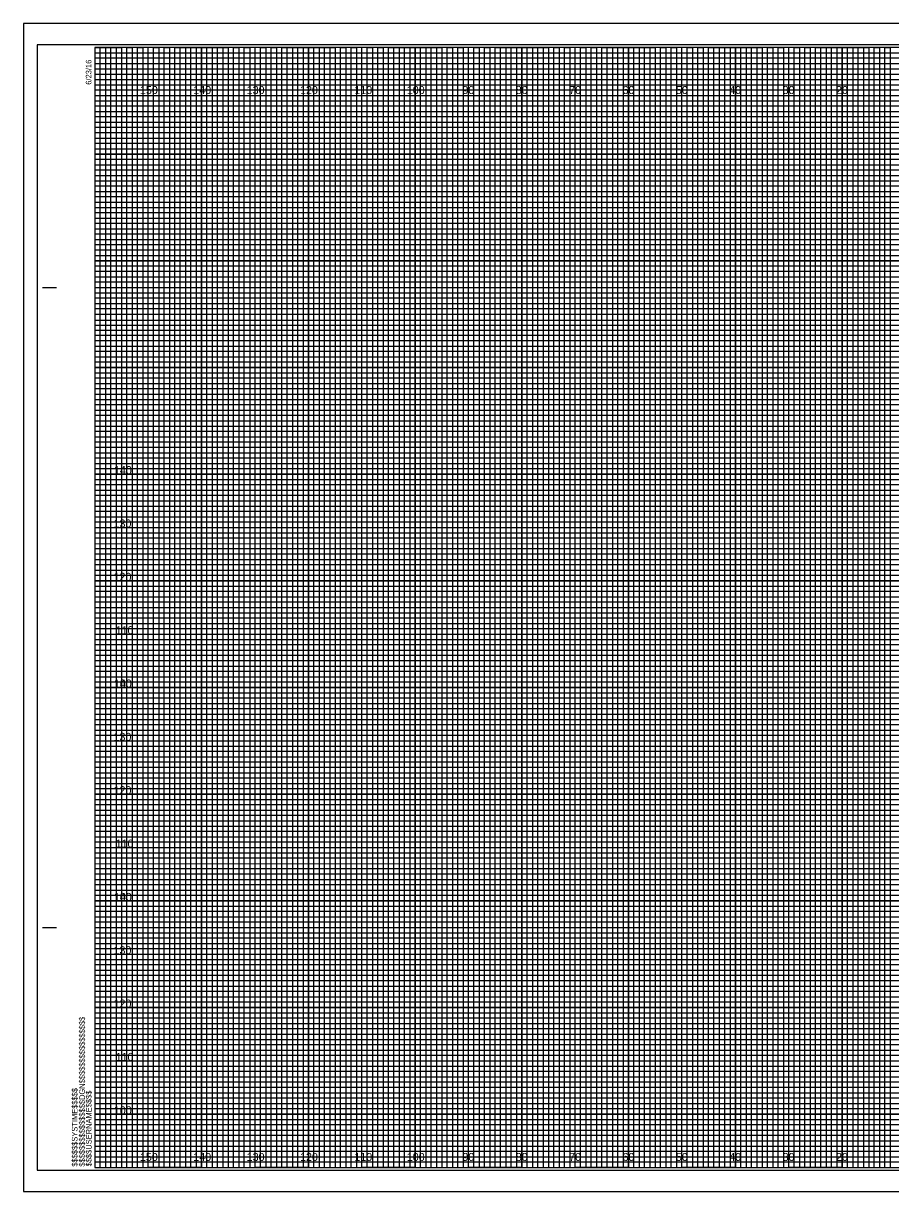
# Model space of a CAD drawing. Extents: x -13 to 323, y -5 to 215.
# Drawn here: x -13.4 to 149.1, y -4.5 to 214.5 of the extents above; entities that cross this region are included whole.
import ezdxf

# ---------------------------------------------------------------- set-up
doc = ezdxf.new("R2010")
doc.units = 0
for name, color, linetype in [('Prop XS Elevation Labels', 7, 'Continuous'), ('Prop XS Offset Labels', 7, 'Continuous'), ('Sheet Cross Section CELL', 7, 'Continuous'), ('Sheet Cross Section Grid Major CELL', 7, 'Continuous'), ('Sheet Cross Section Grid Middle CELL', 7, 'Continuous'), ('Sheet Cross Section Grid Minor 1 CELL', 7, 'Continuous'), ('Sheet Cross Section Grid Minor 2 CELL', 7, 'Continuous'), ('Sheet Cutting Line CELL', 7, 'Continuous'), ('Sheet DOT Grid CELL', 7, 'Continuous'), ('Sheet Plot Border Inside CELL', 7, 'Continuous'), ('Sheet Plot Border Outside CELL', 7, 'Continuous')]:
    doc.layers.add(name, color=color, linetype=linetype)

msp = doc.modelspace()

# ---------------------------------------------------------------- linework, layer by layer
at = {"layer": 'Sheet Cross Section CELL'}
for p, q in [((-9.8, 165), (-7.3, 165)), ((-9.7, 165), (-7.2, 165)), ((-9.8, 45), (-7.3, 45)), ((-9.7, 45), (-7.2, 45)), ((0, 0), (0, 0)), ((0, 0), (0, 0)), ((0, 0), (0, 0)), ((0, 0), (0, 0)), ((0, 0), (0, 0)), ((0, 0), (0, 0)), ((0, 0), (0, 0))]:
    msp.add_line(p, q, dxfattribs=at)
msp.add_lwpolyline([(320, 210), (0, 210), (0, 0), (320, 0)], close=True, dxfattribs=at)
at = {"layer": 'Sheet Cross Section Grid Major CELL'}
for p, q in [((10, 210), (0, 210)), ((10, 0), (10, 210)), ((30, 210), (20, 210)), ((20, 210), (20, 0)), ((30, 0), (30, 210)), ((50, 210), (40, 210)), ((40, 210), (40, 0)), ((50, 0), (50, 210)), ((70, 210), (60, 210)), ((60, 210), (60, 0)), ((70, 0), (70, 210)), ((90, 210), (80, 210)), ((80, 210), (80, 0)), ((90, 0), (90, 210)), ((110, 210), (100, 210)), ((100, 210), (100, 0)), ((110, 0), (110, 210)), ((130, 210), (120, 210)), ((120, 210), (120, 0)), ((130, 0), (130, 210)), ((150, 210), (140, 210)), ((140, 210), (140, 0)), ((20, 0), (10, 0)), ((40, 0), (30, 0)), ((60, 0), (50, 0)), ((80, 0), (70, 0)), ((100, 0), (90, 0)), ((120, 0), (110, 0)), ((140, 0), (130, 0))]:
    msp.add_line(p, q, dxfattribs=at)
for points in [[(0, 200), (320, 200), (320, 190), (0, 190)], [(0, 180), (320, 180), (320, 170), (0, 170)], [(0, 160), (320, 160), (320, 150), (0, 150)], [(0, 140), (320, 140), (320, 130), (0, 130)], [(0, 120), (320, 120), (320, 110), (0, 110)], [(0, 100), (320, 100), (320, 90), (0, 90)], [(0, 80), (320, 80), (320, 70), (0, 70)], [(0, 60), (320, 60), (320, 50), (0, 50)], [(0, 40), (320, 40), (320, 30), (0, 30)], [(0, 20), (320, 20), (320, 10), (0, 10)]]:
    msp.add_lwpolyline(points, dxfattribs=at)
at = {"layer": 'Sheet Cross Section Grid Middle CELL'}
for points in [[(0, 210), (5, 210), (5, 0), (15, 0), (15, 210), (25, 210), (25, 0), (35, 0), (35, 210), (45, 210), (45, 0), (55, 0), (55, 210), (65, 210), (65, 0), (75, 0), (75, 210), (85, 210), (85, 0), (95, 0), (95, 210), (105, 210), (105, 0), (115, 0), (115, 210), (125, 210), (125, 0), (135, 0), (135, 210), (145, 210), (145, 0), (155, 0)], [(0, 205), (275, 205)], [(0, 185), (320, 185), (320, 195), (0, 195)], [(0, 165), (320, 165), (320, 175), (0, 175)], [(0, 145), (320, 145), (320, 155), (0, 155)], [(0, 125), (320, 125), (320, 135), (0, 135)], [(0, 105), (320, 105), (320, 115), (0, 115)], [(0, 85), (320, 85), (320, 95), (0, 95)], [(0, 65), (320, 65), (320, 75), (0, 75)], [(0, 45), (320, 45), (320, 55), (0, 55)], [(0, 25), (320, 25), (320, 35), (0, 35)], [(0, 5), (320, 5), (320, 15), (0, 15)]]:
    msp.add_lwpolyline(points, dxfattribs=at)
at = {"layer": 'Sheet Cross Section Grid Minor 1 CELL'}
for p, q in [((0, 209), (260, 209)), ((260, 207.98), (0, 207.98)), ((0, 207.98), (0, 207)), ((0, 207), (260, 207)), ((260, 205.89), (0, 205.89)), ((0, 205.89), (0, 204)), ((0, 204), (320, 204))]:
    msp.add_line(p, q, dxfattribs=at)
for points in [[(0, 203), (270, 203), (320, 203), (320, 202), (0, 202)], [(0, 201), (320, 201), (320, 199), (0, 199)], [(0, 198), (320, 198), (320, 197), (0, 196.98)], [(0, 196), (320, 196), (320, 194), (0, 194)], [(0, 193), (320, 193), (320, 192), (0, 192)], [(0, 191), (320, 191), (320, 189), (0, 189)], [(0, 188), (320, 188), (320, 187), (0, 187)], [(0, 186), (320, 186), (320, 184), (0, 184)], [(0, 183), (320, 183), (320, 182), (0, 182)], [(0, 181), (320, 181), (320, 179), (0, 179)], [(0, 178), (320, 178), (320, 177), (0, 177)], [(0, 176), (320, 176), (320, 173.95), (320, 173), (320, 172), (0, 172)], [(0, 174), (320, 174), (320, 173), (0, 173)], [(0, 171), (320, 171), (320, 169), (0, 169.03)], [(0, 169.03), (320, 169), (320, 168), (0, 168)], [(0, 167), (320, 167), (320, 166), (0, 166)], [(0, 164), (320, 164), (320, 163), (0, 163)], [(0, 162), (320, 162), (320, 161), (0, 161)], [(-0.07, 158.89), (320, 158.89), (320, 157.88), (-0.07, 157.88)], [(0, 157), (320, 157), (320, 156), (0, 156)], [(0, 154), (320, 154), (320, 153), (0, 153)], [(0, 152), (320, 152), (320, 151), (0, 151)], [(0, 149), (320, 149), (320, 148), (0, 148)], [(0, 147), (320, 147), (320, 146), (0, 146)], [(0, 144), (320, 144), (320, 143), (0, 143)], [(0, 142), (320, 142), (320, 141), (0, 141)], [(0, 139), (320, 139), (319.99, 137.98), (0, 138)], [(0, 137), (320, 137), (320, 136), (0, 136)], [(0, 134), (320, 134), (320, 133), (0, 133)], [(0, 132), (320, 132), (320, 131), (0, 131)], [(0, 129), (320, 129), (320, 128), (0, 128)], [(0, 127), (320, 127), (320, 126), (0, 126)], [(0, 124), (320, 124), (320, 123), (0, 123)], [(0, 122), (320, 122), (320, 121), (0, 121)], [(0, 119), (320, 119), (320, 118), (0, 118)], [(0, 116.99), (320.07, 116.91), (320, 116), (0, 116)], [(0, 114), (320, 114), (320, 113), (0, 113)], [(0, 112), (320, 112), (320, 111), (0, 111)], [(0, 109), (320, 109), (320, 108), (0, 108)], [(0, 107), (320, 107), (320, 106), (0, 106)], [(0, 104), (320, 104), (320, 103), (0, 103)], [(0, 102), (320, 102), (320, 101), (0, 101)], [(0, 99), (320, 99), (320, 98), (0, 98)], [(0, 97), (320, 97), (320, 96), (0, 96)], [(0, 94), (320, 94), (320, 93), (0, 93)], [(0, 92), (320, 92), (320, 91), (0, 91)], [(0, 89), (320, 89), (320, 88), (0, 88)], [(0, 87), (320, 87), (320, 86), (0, 86)], [(0, 84), (320, 84), (320, 83), (0, 83)], [(0, 82), (320, 82), (320, 81), (0, 81)], [(0, 79), (320, 79), (319.99, 77.98), (0, 78)], [(0, 77), (320, 77), (320, 76), (0, 76)], [(0, 74), (320, 74), (320, 73), (0, 73)], [(0, 72), (320, 72), (320, 71), (0, 71)], [(0, 69), (320, 69), (320, 68), (0, 68)], [(0, 67), (320, 67), (320, 66), (0, 66)], [(0, 64), (320, 64), (320, 63), (0, 63)], [(0, 62), (320, 62), (320, 61), (0, 61)], [(0, 59), (320, 59), (320, 58), (0, 58)], [(0, 56.99), (320.07, 56.91), (320, 56), (0, 56)], [(0, 54), (320, 54), (320, 53), (0, 53)], [(0, 52), (320, 52), (320, 51), (0, 51)], [(0, 49), (320, 49), (320, 48), (0, 48)], [(0, 47), (320, 47), (320, 46), (0, 46)], [(0, 44), (320, 44), (320, 43), (0, 43)], [(0, 42), (320, 42), (320, 41), (0, 41)], [(0, 39), (320, 39), (320, 38), (0, 38)], [(0, 37), (320, 37), (320, 36), (0, 36)], [(0, 34), (320, 34), (320, 33), (0, 33)], [(0, 32), (320, 32), (320, 31), (0, 31)], [(0, 29), (320, 29), (320, 28), (0, 28)], [(0, 27), (320, 27), (320, 26), (0, 26)], [(0, 24), (320, 24), (320, 23), (0, 23)], [(0, 22), (320, 22), (320, 21), (0, 21)], [(0, 19), (320, 19), (320, 18), (0, 18)], [(0, 17), (320, 17), (320, 16), (0, 16)], [(0, 14), (320, 14), (320, 13), (0, 13)], [(0, 12), (320, 12), (320, 11), (0, 11)], [(0, 9), (320, 9), (320, 8), (0, 8)], [(0, 7), (320, 7), (320, 6), (0, 6)], [(0, 4), (320, 4), (320, 3), (0, 3)], [(0, 2), (320, 2), (320, 1), (0, 1)]]:
    msp.add_lwpolyline(points, dxfattribs=at)
at = {"layer": 'Sheet Cross Section Grid Minor 2 CELL'}
for points in [[(0, 0), (1, 0), (1, 210), (2, 210), (2, 0)], [(2, 0), (3, 0), (3, 210), (4, 210), (4, 0)], [(5, 0), (6, 0), (6, 210), (7, 210), (7, 0)], [(7, 0), (8, 0), (8, 210), (9, 210), (9, 0)], [(10, 0), (11, 0), (11, 210), (12, 210), (12, 0)], [(12, 0), (13, 0), (13, 210), (14, 210), (14, 0)], [(15, 0), (16, 0), (16, 210), (17, 210), (17, 0)], [(17, 0), (18, 0), (18, 210), (19, 210), (19, 0)], [(20, 0), (21, 0), (21, 210), (22, 210), (22, 0)], [(22, 0), (23, 0), (23, 210), (24, 210), (24, 0)], [(25, 0), (26, 0), (26, 210), (27, 210), (27, 0)], [(27, 0), (28, 0), (28, 210), (29, 210), (29, 0)], [(30, 0), (31, 0), (31, 210), (32, 210), (32, 0)], [(32, 0), (33, 0), (33, 210), (34, 210), (34, 0)], [(35, 0), (36, 0), (36, 210), (37, 210), (37, 0)], [(37, 0), (38, 0), (38, 210), (39, 210), (39, 0)], [(40, 0), (41, 0), (41, 210), (42, 210), (42, 0)], [(42, 0), (43, 0), (43, 210), (44, 210), (44, 0)], [(45, 0), (46, 0), (46, 210), (47, 210), (47, 0)], [(47, 0), (48, 0), (48, 210), (49, 210), (49, 0)], [(50, 0), (51, 0), (51, 210), (52, 210), (52, 0)], [(52, 0), (53, 0), (53, 210), (54, 210), (54, 0)], [(55, 0), (56, 0), (56, 210), (57, 210), (57, 0)], [(57, 0), (58, 0), (58, 210), (59, 210), (59, 0)], [(60, 0), (61, 0), (61, 210), (62, 210), (62, 0)], [(62, 0), (63, 0), (63, 210), (64, 210), (64, 0)], [(65, 0), (66, 0), (66, 210), (67, 210), (67, 0)], [(67, 0), (68, 0), (68, 210), (69, 210), (69, 0)], [(70, 0), (71, 0), (71, 210), (72, 210), (72, 0)], [(72, 0), (73, 0), (73, 210), (74, 210), (74, 0)], [(75, 0), (76, 0), (76, 210), (77, 210), (77, 0)], [(77, 0), (78, 0), (78, 210), (79, 210), (79, 0)], [(80, 0), (81, 0), (81, 210), (82, 210), (82, 0)], [(82, 0), (83, 0), (83, 210), (84, 210), (84, 0)], [(85, 0), (86, 0), (86, 210), (87, 210), (87, 0)], [(87, 0), (88, 0), (88, 210), (89, 210), (89, 0)], [(90, 0), (91, 0), (91, 210), (92, 210), (92, 0)], [(92, 0), (93, 0), (93, 210), (94, 210), (94, 0)], [(95, 0), (96, 0), (96, 210), (97, 210), (97, 0)], [(97, 0), (98, 0), (98, 210), (99, 210), (99, 0)], [(100, 0), (101, 0), (101, 210), (102, 210), (102, 0)], [(102, 0), (103, 0), (103, 210), (104, 210), (104, 0)], [(105, 0), (106, 0), (106, 210), (107, 210), (107, 0)], [(107, 0), (108, 0), (108, 210), (109, 210), (109, 0)], [(110, 0), (111, 0), (111, 210), (112, 210), (112, 0)], [(112, 0), (113, 0), (113, 210), (114, 210), (114, 0)], [(115, 0), (116, 0), (116, 210), (117, 210), (117, 0)], [(117, 0), (118, 0), (118, 210), (119, 210), (119, 0)], [(120, 0), (121, 0), (121, 210), (122, 210), (122, 0)], [(122, 0), (123, 0), (123, 210), (124, 210), (124, 0)], [(125, 0), (126, 0), (126, 210), (127, 210), (127, 0)], [(127, 0), (128, 0), (128, 210), (129, 210), (129, 0)], [(130, 0), (131, 0), (131, 210), (132, 210), (132, 0)], [(132, 0), (133, 0), (133, 210), (134, 210), (134, 0)], [(135, 0), (136, 0), (136, 210), (137, 210), (137, 0)], [(137, 0), (138, 0), (138, 210), (139, 210), (139, 0)], [(140, 0), (141, 0), (141, 210), (142, 210), (142, 0)], [(142, 0), (143, 0), (143, 210), (144, 210), (144, 0)], [(145, 0), (146, 0), (146, 210), (147, 210), (147, 0)], [(147, 0), (148, 0), (148, 210), (149, 210), (149, 0)]]:
    msp.add_lwpolyline(points, dxfattribs=at)
at = {"layer": 'Sheet Cutting Line CELL'}
for p, q in [((323.3, 214.5), (-13.4, 214.5)), ((-13.4, 214.5), (-13.4, -4.5)), ((-13.4, -4.5), (323.3, -4.5))]:
    msp.add_line(p, q, dxfattribs=at)
at = {"layer": 'Sheet DOT Grid CELL'}
for p, q in [((10, 0), (10, 210)), ((20, 0), (20, 210)), ((30, 0), (30, 210)), ((40, 0), (40, 210)), ((50, 0), (50, 210)), ((60, 0), (60, 210)), ((70, 0), (70, 210)), ((80, 0), (80, 210)), ((90, 0), (90, 210)), ((100, 0), (100, 210)), ((110, 0), (110, 210)), ((120, 0), (120, 210)), ((130, 0), (130, 210)), ((140, 0), (140, 210)), ((0, 200), (320, 200)), ((0, 190), (320, 190)), ((0, 180), (320, 180)), ((0, 170), (320, 170)), ((0, 160), (320, 160)), ((0, 150), (320, 150)), ((0, 140), (320, 140)), ((0, 130), (320, 130)), ((0, 120), (320, 120)), ((0, 110), (320, 110)), ((0, 100), (320, 100)), ((0, 90), (320, 90)), ((0, 80), (320, 80)), ((0, 70), (320, 70)), ((0, 60), (320, 60)), ((0, 50), (320, 50)), ((0, 40), (320, 40)), ((0, 30), (320, 30)), ((0, 20), (320, 20)), ((0, 10), (320, 10))]:
    msp.add_line(p, q, dxfattribs=at)
at = {"layer": 'Sheet Plot Border Inside CELL'}
msp.add_lwpolyline([(-10.8, -0.5), (322.4, -0.5), (322.4, 210.5), (-10.8, 210.5)], close=True, dxfattribs=at)
at = {"layer": 'Sheet Plot Border Outside CELL'}
msp.add_lwpolyline([(-13.4, -4.5), (323.3, -4.5), (323.3, 214.5), (-13.4, 214.5)], close=True, dxfattribs=at)

# ---------------------------------------------------------------- texts
at = {"layer": 'Prop XS Elevation Labels'}
for s, p in [('140', (3.57, 130)), ('130', (3.49, 120)), ('120', (3.5, 110)), ('110', (3.88, 100)), ('100', (3.55, 90)), ('140', (3.57, 90)), ('130', (3.49, 80)), ('120', (3.5, 70)), ('110', (3.88, 60)), ('100', (3.55, 50)), ('140', (3.57, 50)), ('130', (3.49, 40)), ('120', (3.5, 30)), ('110', (3.88, 20)), ('100', (3.55, 10))]:
    msp.add_text(s, height=1.5, dxfattribs=at).set_placement(p)
at = {"layer": 'Prop XS Offset Labels'}
for s, p in [('150', (8.44, 201.25)), ('140', (18.44, 201.25)), ('130', (28.44, 201.25)), ('120', (38.44, 201.25)), ('110', (48.62, 201.25)), ('100', (58.44, 201.25)), ('90', (68.86, 201.25)), ('80', (78.86, 201.25)), ('70', (88.86, 201.25)), ('60', (98.86, 201.25)), ('50', (108.86, 201.25)), ('40', (118.86, 201.25)), ('30', (128.86, 201.25)), ('20', (138.86, 201.25)), ('150', (8.44, 1.25)), ('140', (18.44, 1.25)), ('130', (28.44, 1.25)), ('120', (38.44, 1.25)), ('110', (48.62, 1.25)), ('100', (58.44, 1.25)), ('90', (68.86, 1.25)), ('80', (78.86, 1.25)), ('70', (88.86, 1.25)), ('60', (98.86, 1.25)), ('50', (108.86, 1.25)), ('40', (118.86, 1.25)), ('30', (128.86, 1.25)), ('20', (138.86, 1.25))]:
    msp.add_text(s, height=1.5, dxfattribs=at).set_placement(p)
at = {"layer": 'Sheet Cross Section CELL'}
for s, p in [('6/23/16', (-0.65, 203)), ('$$$$$$$$$$$$$$$$DGN$$$$$$$$$$$$$$$$', (-1.88, 0.18)), ('$$$$$$SYSTIME$$$$$', (-3.26, 0.18)), ('$$$$USERNAME$$$$', (-0.62, 0.23))]:
    msp.add_text(s, height=1.05, rotation=90, dxfattribs=at).set_placement(p)

doc.saveas('drawing.dxf')
